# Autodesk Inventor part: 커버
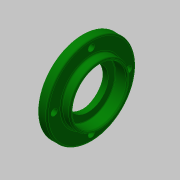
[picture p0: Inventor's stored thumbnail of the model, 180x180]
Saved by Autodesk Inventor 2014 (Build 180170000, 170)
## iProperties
Created: 2018-11
Part Number: 커버
Material: 알루미늄 6061
Document SubType Name: Modeling
Designer: mduedu
Density: 1 g/cm^3
Appearance: 진녹색
Author: mduedu
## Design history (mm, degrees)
sketch "스케치1"
  geometry: L1 (0, 0)-(2, 0); L2 (2, 0)-(2, 20); L3 (2, 20)-(0, 20); L4 (0, 20)-(0, 0); L5 (2, 0)-(8, 0); L6 (8, 0)-(8, 31); L7 (8, 31)-(2, 31); L8 (2, 31)-(2, 0); L9 (8, 0)-(14, 0); L10 (14, 0)-(14, 21); L11 (14, 21)-(8, 21); L12 (8, 21)-(8, 0)
  constraints: 24 end point, 6 parallel, 3 horizontal, 3 perpendicular
  dimensions: "d0" = 62 diameter of L7 L5; "d2" = 42 diameter of L11 L9; "d3" = 40 diameter of L3 L1; "d4" = 2 distance of L2.end L3.end; "d5" = 6 distance of L6.end L7.end; "d6" = 14 distance between parallel lines of L10 L4
revolve "회전1" sketch "스케치1" stored, may be unused: angle "d7" = 90 deg
sketch "스케치2"
  geometry: L1 (0, -20)-(0, 20) reference; L2 (0, 20)-(2, 20) reference; L3 (2, 20)-(2, 31) reference; L4 (2, 31)-(8, 31) reference; L5 (8, 31)-(8, 21) reference; L6 (8, 21)-(14, 21) reference; L7 (14, 21)-(14, -21) reference; L8 (14, -21)-(8, -21) reference; L9 (8, -21)-(8, -31) reference; L10 (8, -31)-(2, -31) reference; L11 (2, -31)-(2, -20) reference; L12 (2, -20)-(0, -20) reference; L13 (0, 0)-(2, 0); L14 (2, 0)-(2, 16.5); L15 (2, 16.5)-(0, 16.5); L16 (0, 16.5)-(0, 0); L17 (2, 0)-(5.7, 0); L18 (5.7, 0)-(5.7, 14); L19 (5.7, 14)-(2, 14); L20 (2, 14)-(2, 0); L21 (5.7, 0)-(14, 0); L22 (14, 0)-(14, 19); L23 (14, 19)-(5.7, 19); L24 (5.7, 19)-(5.7, 0)
  constraints: 24 end point, 6 parallel, 3 horizontal, 3 perpendicular, 1 point on line
  dimensions: "d8" = 38 diameter of L23 L21; "d10" = 28 diameter of L19 L17; "d11" = 33 diameter of L15 L13; "d12" = 2 distance of L14.end L15.end; "d13" = 8.3 distance of L22.end L23.end
revolve "회전2" sketch "스케치2" stored, may be unused: angle "d14" = 90 deg
fillet "모깎기1" dims "d15" = 0.3
chamfer "모따기1" distance "d16" = 0.8; stored, may be unused: second distance "d17" = 2, angle "d18" = 30 deg
fillet "모깎기2" dims "d19" = 1
chamfer "모따기2" distance "d20" = 0.5; stored, may be unused: second distance "d21" = 2, angle "d22" = 30 deg
sketch "스케치3" dims "d23" = 52
  geometry: 6 further points
  constraints: 2 vertical alignment, 1 coincident, 7 other
  dimensions: "d26" = 360 deg dimension on point (0, 0) point (0, 26) (derived)
sketch "스케치4"
  geometry: 4 further points
  constraints: 4 other
hole "구멍1" sketch "스케치4" at (-26, 0), (0, -26), (26, 0), (0, 26) diameter "d28" = 4.5; stored, may be unused: countersink angle "d32" = 90 deg, drill point angle "d34" = 0 deg; dims "d29" = 6, "d30" = 8, "d31" = 4.6, "d33" = 8
node "솔리드1"
node "절단 모서리 투영1"
